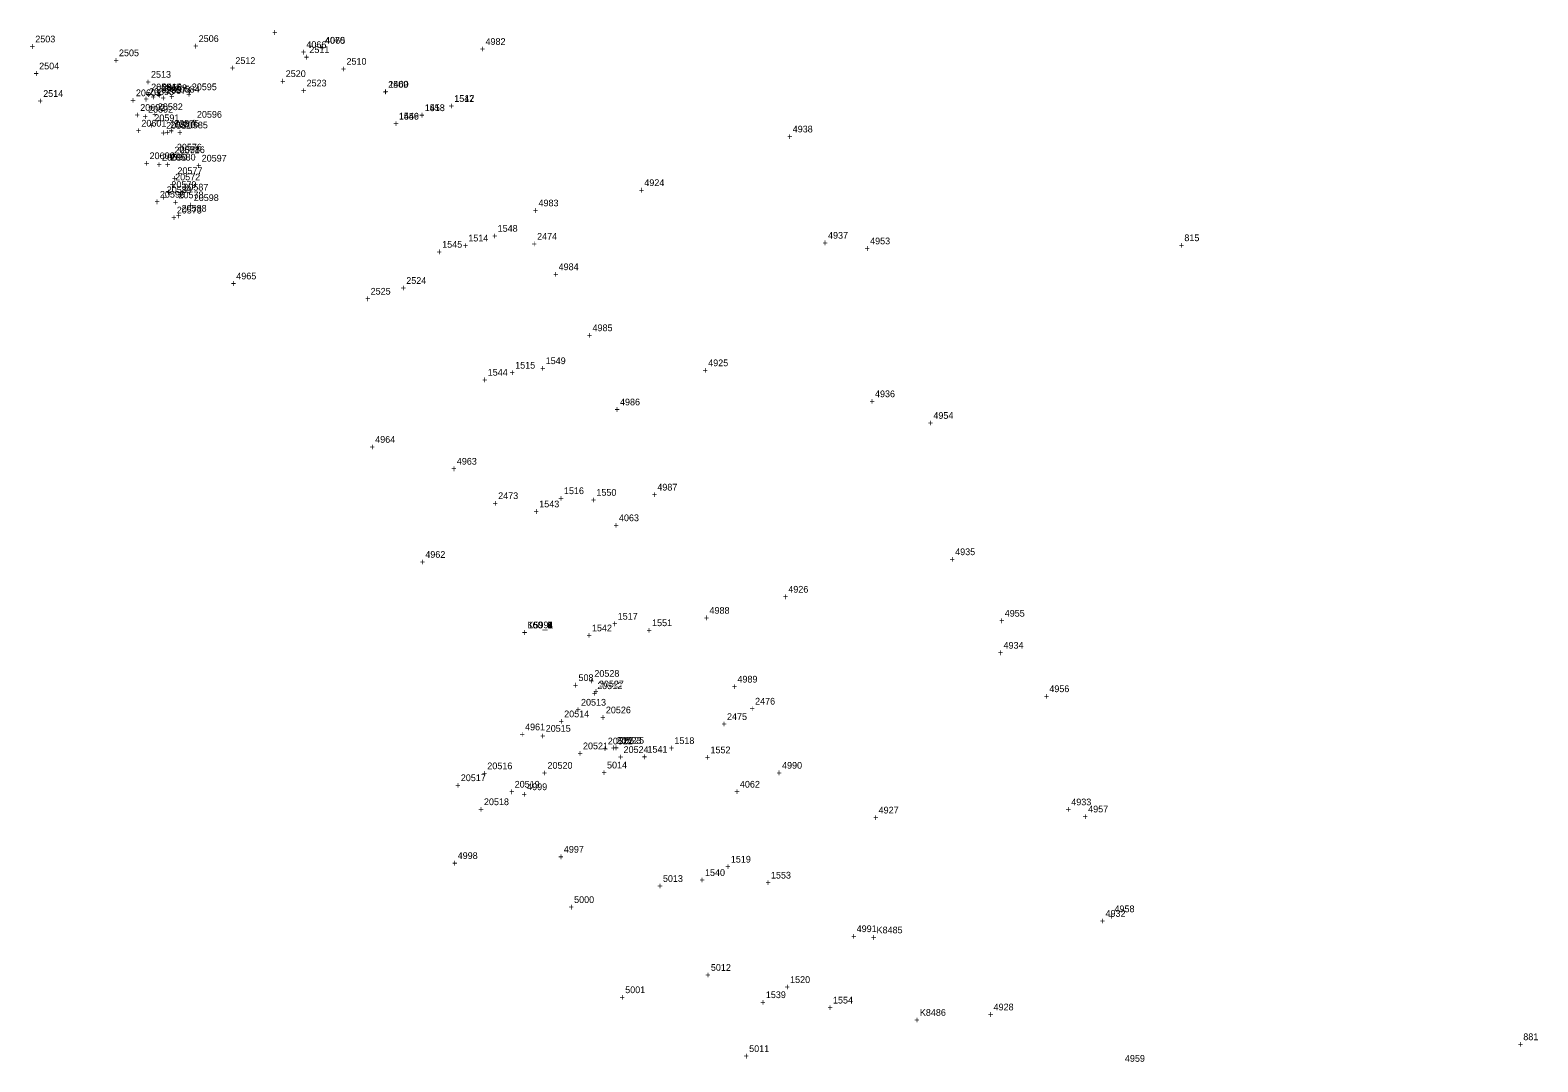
# Model space of a CAD drawing. Extents: x 1036751 to 1042192, y 772604 to 785439.
# Drawn here: x 1038464 to 1039024, y 778195 to 778579 of the extents above; entities that cross this region are included whole.
import ezdxf

# ---------------------------------------------------------------- set-up
doc = ezdxf.new("R2010")
doc.units = 0
for name, color, linetype in [('S_Control_Temp_Traverse', 7, 'Continuous'), ('S_Control_Traverse_Point', 7, 'Continuous'), ('S_Drainage_Culvert_Top', 7, 'Continuous'), ('S_Drainage_Ditch_Line', 7, 'Continuous'), ('S_Drainage_Invert', 7, 'Continuous'), ('S_Ground_Elevation', 7, 'Continuous'), ('S_Property_BlazedLine', 7, 'Continuous'), ('S_Property_IronPipeFound', 7, 'Continuous'), ('S_Roadway_Centerline', 7, 'Continuous'), ('S_Roadway_Drive_Gravel', 7, 'Continuous'), ('S_Roadway_Edge_Pavement', 7, 'Continuous'), ('S_Roadway_Edge_Shoulder', 7, 'Continuous'), ('S_Traffic_Sign_SinglePost', 7, 'Continuous'), ('S_Trees_Conifer_Pay', 7, 'Continuous'), ('S_Trees_TreeLine', 7, 'Continuous'), ('S_Utilities_GuyWire3', 7, 'Continuous'), ('S_Utilities_Pole_Brace3', 7, 'Continuous'), ('S_Utilities_Pole_Power', 7, 'Continuous'), ('S_Utilities_Pole_Support3', 7, 'Continuous'), ('S_Utilities_UG_Water_Line', 7, 'Continuous')]:
    doc.layers.add(name, color=color, linetype=linetype)

msp = doc.modelspace()

# ---------------------------------------------------------------- texts
at = {"layer": 'S_Control_Temp_Traverse'}
for s, p in [('+', (1038890.89, 778497.76)), ('+', (1038890.89, 778497.76)), ('815', (1038892.96, 778500.51)), ('815', (1038892.96, 778500.51)), ('160', (1038648.85, 778356.47)), ('160_1', (1038648.85, 778356.47)), ('160_3', (1038648.85, 778356.47)), ('160_2', (1038648.85, 778356.47)), ('160_5', (1038648.85, 778356.47)), ('160_4', (1038648.85, 778356.47)), ('160_7', (1038648.85, 778356.47)), ('160_6', (1038648.85, 778356.47)), ('160_9', (1038648.85, 778356.47)), ('160_8', (1038648.85, 778356.47)), ('+', (1038646.79, 778353.72)), ('+', (1038646.79, 778353.72)), ('+', (1038646.79, 778353.72)), ('+', (1038646.79, 778353.72)), ('+', (1038646.79, 778353.72)), ('+', (1038646.79, 778353.72)), ('+', (1038646.79, 778353.72)), ('+', (1038646.79, 778353.72)), ('+', (1038646.79, 778353.72)), ('+', (1038646.79, 778353.72)), ('+', (1039016.86, 778200.59)), ('+', (1039016.86, 778200.59)), ('881', (1039018.92, 778203.34)), ('881', (1039018.92, 778203.34))]:
    msp.add_text(s, height=2.5, dxfattribs=at).set_placement(p)
at = {"layer": 'S_Control_Traverse_Point'}
for s, p in [('+', (1038665.71, 778334.15)), ('+', (1038665.71, 778334.15)), ('+', (1038665.71, 778334.15)), ('+', (1038665.71, 778334.15)), ('+', (1038665.71, 778334.15)), ('+', (1038665.71, 778334.15)), ('+', (1038665.71, 778334.15)), ('+', (1038665.71, 778334.15)), ('+', (1038665.71, 778334.15)), ('+', (1038665.71, 778334.15)), ('+', (1038665.71, 778334.15)), ('+', (1038665.71, 778334.15)), ('+', (1038665.71, 778334.15)), ('+', (1038665.71, 778334.15)), ('508', (1038667.77, 778336.9)), ('508', (1038667.77, 778336.9)), ('508', (1038667.77, 778336.9)), ('508', (1038667.77, 778336.9)), ('508', (1038667.77, 778336.9)), ('508', (1038667.77, 778336.9)), ('508', (1038667.77, 778336.9)), ('508', (1038667.77, 778336.9)), ('508', (1038667.77, 778336.9)), ('508', (1038667.77, 778336.9)), ('508', (1038667.77, 778336.9)), ('508', (1038667.77, 778336.9)), ('508', (1038667.77, 778336.9)), ('508', (1038667.77, 778336.9))]:
    msp.add_text(s, height=2.5, dxfattribs=at).set_placement(p)
at = {"layer": 'S_Drainage_Culvert_Top'}
for s, p in [('2516', (1038512.85, 778556.64)), ('+', (1038510.79, 778553.89))]:
    msp.add_text(s, height=2.5, dxfattribs=at).set_placement(p)
at = {"layer": 'S_Drainage_Ditch_Line'}
for s, p in [('+', (1038510.96, 778553.55)), ('20569', (1038513.02, 778556.3)), ('20570', (1038516.05, 778542.54)), ('+', (1038513.99, 778539.79)), ('+', (1038515.55, 778530.4)), ('20571', (1038517.61, 778533.15)), ('20572', (1038517.87, 778523.14)), ('+', (1038515.81, 778520.39)), ('+', (1038516.41, 778508.05)), ('20573', (1038518.47, 778510.8))]:
    msp.add_text(s, height=2.5, dxfattribs=at).set_placement(p)
at = {"layer": 'S_Drainage_Invert'}
for s, p in [('+', (1038510.79, 778553.87)), ('2515', (1038512.85, 778556.62))]:
    msp.add_text(s, height=2.5, dxfattribs=at).set_placement(p)
at = {"layer": 'S_Ground_Elevation'}
for s, p in [('4982', (1038633.22, 778573.49)), ('+', (1038631.16, 778570.74)), ('20595', (1038524.05, 778556.66)), ('+', (1038501.22, 778551.67)), ('20603', (1038503.28, 778554.42)), ('+', (1038506.1, 778552.13)), ('+', (1038506.9, 778553.85)), ('20593', (1038508.16, 778554.88)), ('+', (1038508.76, 778552.89)), ('20594', (1038508.96, 778556.6)), ('20583', (1038510.83, 778555.64)), ('+', (1038512.46, 778552.56)), ('20574', (1038514.52, 778555.31)), ('+', (1038515.61, 778553.05)), ('20584', (1038517.67, 778555.8)), ('+', (1038521.99, 778553.91)), ('+', (1038502.82, 778546.23)), ('20602', (1038504.88, 778548.98)), ('20592', (1038507.82, 778548.32)), ('+', (1038509.34, 778546.5)), ('20582', (1038511.41, 778549.25)), ('20596', (1038525.95, 778546.41)), ('+', (1038503.25, 778540.37)), ('20601', (1038505.31, 778543.12)), ('+', (1038505.76, 778545.57)), ('+', (1038508.07, 778542.37)), ('20591', (1038510.13, 778545.12)), ('20581', (1038514.55, 778542.32)), ('+', (1038515.44, 778540.33)), ('20575', (1038517.5, 778543.08)), ('20585', (1038520.72, 778542.45)), ('+', (1038523.89, 778543.66)), ('4938', (1038747.39, 778540.95)), ('+', (1038512.49, 778539.57)), ('20576', (1038518.5, 778534.23)), ('+', (1038518.66, 778539.7)), ('+', (1038745.33, 778538.2)), ('20600', (1038508.36, 778531.01)), ('20590', (1038512.98, 778530.48)), ('20580', (1038516.17, 778530.5)), ('+', (1038516.43, 778531.48)), ('+', (1038517.53, 778530.51)), ('20586', (1038519.59, 778533.26)), ('20597', (1038527.72, 778530.11)), ('+', (1038506.3, 778528.26)), ('+', (1038510.92, 778527.73)), ('+', (1038514.11, 778527.75)), ('20577', (1038518.71, 778525.45)), ('+', (1038525.66, 778527.36)), ('20589', (1038514.73, 778518.37)), ('20579', (1038516.47, 778520.29)), ('+', (1038516.64, 778522.7)), ('20587', (1038520.9, 778519.33)), ('+', (1038690.17, 778518.26)), ('4924', (1038692.24, 778521.01)), ('+', (1038510.15, 778513.94)), ('20599', (1038512.21, 778516.69)), ('+', (1038512.67, 778515.62)), ('+', (1038514.41, 778517.54)), ('+', (1038517.03, 778513.71)), ('+', (1038518.84, 778516.58)), ('20578', (1038519.09, 778516.46)), ('+', (1038522.71, 778512.67)), ('20598', (1038524.77, 778515.42)), ('4983', (1038652.91, 778513.46)), ('+', (1038518.19, 778508.73)), ('20588', (1038520.25, 778511.48)), ('+', (1038650.85, 778510.71)), ('4937', (1038760.52, 778501.42)), ('+', (1038758.46, 778498.67)), ('+', (1038774.1, 778496.59)), ('4953', (1038776.16, 778499.34)), ('4984', (1038660.39, 778489.71)), ('4965', (1038540.58, 778486.3)), ('+', (1038658.33, 778486.96)), ('+', (1038538.52, 778483.55)), ('4985', (1038672.99, 778467.03)), ('+', (1038670.93, 778464.28)), ('+', (1038713.92, 778451.25)), ('4925', (1038715.98, 778454)), ('4986', (1038683.2, 778439.44)), ('+', (1038775.91, 778439.72)), ('4936', (1038777.97, 778442.47)), ('+', (1038681.13, 778436.69)), ('4954', (1038799.67, 778434.43)), ('+', (1038797.61, 778431.68)), ('+', (1038590.16, 778422.78)), ('4964', (1038592.22, 778425.53)), ('4987', (1038697.07, 778407.76)), ('+', (1038695.01, 778405.01)), ('4935', (1038807.77, 778383.73)), ('+', (1038608.78, 778379.98)), ('4962', (1038610.84, 778382.73)), ('+', (1038805.7, 778380.98)), ('+', (1038743.69, 778367.04)), ('4926', (1038745.75, 778369.79)), ('4988', (1038716.47, 778361.94)), ('4955', (1038826.19, 778360.85)), ('+', (1038714.41, 778359.19)), ('+', (1038824.13, 778358.1)), ('+', (1038823.69, 778346.2)), ('4934', (1038825.75, 778348.95)), ('+', (1038724.79, 778333.59)), ('4989', (1038726.85, 778336.34)), ('4956', (1038842.77, 778332.78)), ('+', (1038840.7, 778330.03)), ('4961', (1038647.92, 778318.59)), ('+', (1038645.86, 778315.84)), ('+', (1038676.32, 778301.65)), ('5014', (1038678.38, 778304.4)), ('+', (1038741.37, 778301.55)), ('4990', (1038743.43, 778304.3)), ('4999', (1038648.7, 778296.33)), ('+', (1038646.64, 778293.58)), ('4933', (1038850.92, 778290.7)), ('4957', (1038857.2, 778288.05)), ('+', (1038777.26, 778284.9)), ('4927', (1038779.32, 778287.65)), ('+', (1038848.86, 778287.95)), ('+', (1038855.14, 778285.3)), ('5013', (1038699.15, 778262.21)), ('5000', (1038666.14, 778254.37)), ('+', (1038697.09, 778259.46)), ('+', (1038664.08, 778251.62)), ('4932', (1038863.66, 778249.22)), ('4958', (1038866.99, 778250.93)), ('4991', (1038771.16, 778243.53)), ('+', (1038861.6, 778246.47)), ('+', (1038864.93, 778248.18)), ('+', (1038769.1, 778240.78)), ('5012', (1038716.97, 778229.13)), ('5001', (1038685.13, 778220.83)), ('+', (1038714.91, 778226.38)), ('+', (1038683.06, 778218.08)), ('+', (1038819.99, 778211.67)), ('4928', (1038822.05, 778214.42)), ('5011', (1038731.2, 778198.95)), ('+', (1038729.14, 778196.2)), ('4959', (1038870.86, 778195.31))]:
    msp.add_text(s, height=2.5, dxfattribs=at).set_placement(p)
at = {"layer": 'S_Property_BlazedLine'}
for s, p in [('4997', (1038662.34, 778273.07)), ('+', (1038620.81, 778267.97)), ('4998', (1038622.87, 778270.72)), ('+', (1038660.28, 778270.32))]:
    msp.add_text(s, height=2.5, dxfattribs=at).set_placement(p)
at = {"layer": 'S_Property_IronPipeFound'}
for s, p in [('4963', (1038622.55, 778417.39)), ('+', (1038620.49, 778414.64))]:
    msp.add_text(s, height=2.5, dxfattribs=at).set_placement(p)
at = {"layer": 'S_Roadway_Centerline'}
for s, p in [('2506', (1038526.61, 778574.58)), ('+', (1038553.89, 778576.9)), ('2505', (1038496.98, 778569.29)), ('+', (1038524.55, 778571.83)), ('2504', (1038467.32, 778564.41)), ('+', (1038494.92, 778566.54)), ('+', (1038465.26, 778561.66)), ('+', (1038608.58, 778546.16)), ('+', (1038608.6, 778546.12)), ('1458', (1038610.64, 778548.91)), ('1513', (1038610.66, 778548.87)), ('+', (1038624.75, 778497.65)), ('1514', (1038626.81, 778500.4)), ('1515', (1038644.24, 778453.12)), ('+', (1038642.18, 778450.37)), ('1516', (1038662.36, 778406.43)), ('+', (1038660.3, 778403.68)), ('+', (1038680.29, 778356.99)), ('1517', (1038682.35, 778359.74)), ('+', (1038701.35, 778310.75)), ('1518', (1038703.41, 778313.5)), ('+', (1038722.33, 778266.64)), ('1519', (1038724.39, 778269.39)), ('+', (1038744.36, 778221.87)), ('1520', (1038746.42, 778224.62))]:
    msp.add_text(s, height=2.5, dxfattribs=at).set_placement(p)
at = {"layer": 'S_Roadway_Drive_Gravel'}
for s, p in [('20512', (1038674.76, 778333.9)), ('20513', (1038668.71, 778327.76)), ('+', (1038672.7, 778331.15)), ('20514', (1038662.45, 778323.44)), ('+', (1038666.65, 778325.01)), ('20515', (1038655.59, 778318.04)), ('+', (1038660.39, 778320.69)), ('+', (1038653.53, 778315.29)), ('20521', (1038669.44, 778311.54)), ('+', (1038676.61, 778310.58)), ('20522', (1038678.67, 778313.33)), ('+', (1038679.87, 778310.84)), ('20523', (1038681.93, 778313.59)), ('+', (1038667.38, 778308.79)), ('20517', (1038624.03, 778299.68)), ('+', (1038631.82, 778301.36)), ('20516', (1038633.88, 778304.11)), ('+', (1038654.18, 778301.52)), ('20520', (1038656.24, 778304.27)), ('+', (1038621.97, 778296.93)), ('+', (1038641.99, 778294.51)), ('20519', (1038644.05, 778297.26)), ('20518', (1038632.63, 778290.75)), ('+', (1038630.56, 778288))]:
    msp.add_text(s, height=2.5, dxfattribs=at).set_placement(p)
at = {"layer": 'S_Roadway_Edge_Pavement'}
for s, p in [('2503', (1038465.87, 778574.44)), ('+', (1038463.81, 778571.69)), ('2511', (1038567.74, 778570.48)), ('+', (1038538.18, 778563.67)), ('2512', (1038540.24, 778566.42)), ('+', (1038565.68, 778567.73)), ('+', (1038579.49, 778563.37)), ('2510', (1038581.55, 778566.12)), ('+', (1038506.82, 778558.53)), ('2513', (1038508.88, 778561.28)), ('2509', (1038597.05, 778557.58)), ('1460', (1038597.2, 778557.63)), ('2514', (1038468.82, 778554.18)), ('+', (1038594.99, 778554.83)), ('+', (1038595.14, 778554.88)), ('1512', (1038621.59, 778552.31)), ('1547', (1038621.61, 778552.29)), ('+', (1038466.75, 778551.43)), ('1546', (1038601.01, 778545.75)), ('1459', (1038601.03, 778545.71)), ('+', (1038619.53, 778549.56)), ('+', (1038619.54, 778549.54)), ('+', (1038598.95, 778543)), ('+', (1038598.97, 778542.96)), ('+', (1038635.66, 778501.25)), ('1548', (1038637.72, 778504)), ('1545', (1038617.12, 778498.07)), ('+', (1038615.06, 778495.32)), ('1544', (1038634.04, 778450.47)), ('+', (1038653.52, 778452.03)), ('1549', (1038655.58, 778454.78)), ('+', (1038631.97, 778447.72)), ('1550', (1038674.43, 778405.81)), ('1543', (1038653.18, 778401.52)), ('+', (1038672.36, 778403.06)), ('+', (1038651.12, 778398.77)), ('K5991', (1038648.81, 778356.53)), ('1542', (1038672.77, 778355.41)), ('1551', (1038695.12, 778357.33)), ('+', (1038646.75, 778353.78)), ('+', (1038670.71, 778352.66)), ('+', (1038693.06, 778354.58)), ('1541', (1038693.4, 778310.26)), ('+', (1038691.34, 778307.51)), ('+', (1038714.76, 778307.3)), ('1552', (1038716.82, 778310.05)), ('+', (1038712.72, 778261.67)), ('1540', (1038714.78, 778264.42)), ('+', (1038737.24, 778260.7)), ('1553', (1038739.3, 778263.45)), ('+', (1038735.34, 778216.24)), ('1539', (1038737.4, 778218.99)), ('1554', (1038762.35, 778216.98)), ('+', (1038760.29, 778214.23))]:
    msp.add_text(s, height=2.5, dxfattribs=at).set_placement(p)
at = {"layer": 'S_Roadway_Edge_Shoulder'}
for s, p in [('20528', (1038673.67, 778338.49)), ('+', (1038671.61, 778335.74)), ('20527', (1038675.33, 778334.57)), ('+', (1038673.27, 778331.82)), ('+', (1038675.89, 778322.16)), ('20526', (1038677.95, 778324.91)), ('+', (1038680.79, 778310.86)), ('20525', (1038682.85, 778313.61)), ('20524', (1038684.53, 778310.16)), ('+', (1038682.47, 778307.41))]:
    msp.add_text(s, height=2.5, dxfattribs=at).set_placement(p)
at = {"layer": 'S_Traffic_Sign_SinglePost'}
for s, p in [('+', (1038556.9, 778558.8)), ('2520', (1038558.96, 778561.55)), ('+', (1038635.86, 778401.83)), ('2473', (1038637.92, 778404.58))]:
    msp.add_text(s, height=2.5, dxfattribs=at).set_placement(p)
at = {"layer": 'S_Trees_Conifer_Pay'}
for s, p in [('2523', (1038566.71, 778558.06)), ('+', (1038564.65, 778555.31))]:
    msp.add_text(s, height=2.5, dxfattribs=at).set_placement(p)
at = {"layer": 'S_Trees_TreeLine'}
for s, p in [('K8485', (1038778.56, 778243.08)), ('+', (1038776.5, 778240.33)), ('K8486', (1038794.65, 778212.39)), ('+', (1038792.59, 778209.64))]:
    msp.add_text(s, height=2.5, dxfattribs=at).set_placement(p)
at = {"layer": 'S_Utilities_GuyWire3'}
for s, p in [('2525', (1038590.52, 778480.62)), ('+', (1038588.46, 778477.87))]:
    msp.add_text(s, height=2.5, dxfattribs=at).set_placement(p)
at = {"layer": 'S_Utilities_Pole_Brace3'}
for s, p in [('2476', (1038733.41, 778328.16)), ('+', (1038731.35, 778325.41))]:
    msp.add_text(s, height=2.5, dxfattribs=at).set_placement(p)
at = {"layer": 'S_Utilities_Pole_Power'}
for s, p in [('2474', (1038652.38, 778501.04)), ('+', (1038650.32, 778498.29)), ('2475', (1038722.97, 778322.44)), ('+', (1038720.91, 778319.69))]:
    msp.add_text(s, height=2.5, dxfattribs=at).set_placement(p)
at = {"layer": 'S_Utilities_Pole_Support3'}
for s, p in [('2524', (1038603.76, 778484.62)), ('+', (1038601.7, 778481.87))]:
    msp.add_text(s, height=2.5, dxfattribs=at).set_placement(p)
at = {"layer": 'S_Utilities_UG_Water_Line'}
for s, p in [('4070', (1038573.52, 778573.98)), ('4065', (1038573.64, 778573.92)), ('+', (1038564.56, 778569.61)), ('4066', (1038566.62, 778572.36)), ('+', (1038571.46, 778571.23)), ('+', (1038571.58, 778571.17)), ('4063', (1038682.81, 778396.36)), ('+', (1038680.75, 778393.61)), ('+', (1038725.71, 778294.52)), ('4062', (1038727.77, 778297.27))]:
    msp.add_text(s, height=2.5, dxfattribs=at).set_placement(p)

doc.saveas('drawing.dxf')
